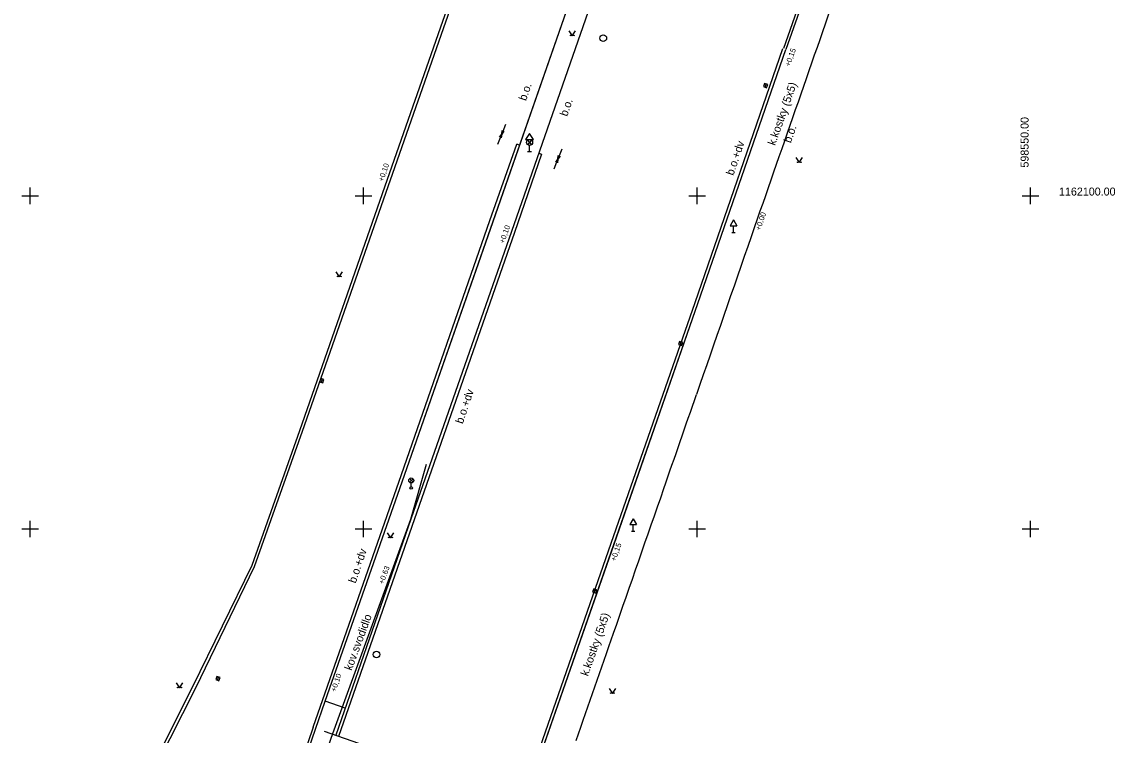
# Model space of a CAD drawing. Extents: x -599151 to -598424, y -1163476 to -1161924.
# Drawn here: x -598625.6 to -598543.7, y -1162140.5 to -1162086.9 of the extents above; entities that cross this region are included whole.
import ezdxf

# ---------------------------------------------------------------- set-up
doc = ezdxf.new("R2010")
doc.units = 0
for name, color, linetype in [('Vrstva 14', 7, 'Continuous'), ('Vrstva 19', 7, 'Continuous'), ('Vrstva 21', 7, 'Continuous'), ('Vrstva 25', 7, 'Continuous'), ('Vrstva 29', 7, 'Continuous'), ('Vrstva 44', 7, 'Continuous'), ('Vrstva 49', 7, 'Continuous'), ('Vrstva 50', 7, 'Continuous'), ('Vrstva 52', 7, 'Continuous'), ('Vrstva 62', 7, 'Continuous'), ('Vrstva 63', 7, 'Continuous'), ('Vrstva 7', 7, 'Continuous')]:
    doc.layers.add(name, color=color, linetype=linetype)

msp = doc.modelspace()

# ---------------------------------------------------------------- linework, layer by layer
at = {"layer": 'Vrstva 14'}
for points in [[(-598584.609, -1162087.607), (-598584.359, -1162087.982), (-598584.109, -1162087.607)], [(-598567.583, -1162097.133), (-598567.333, -1162097.508), (-598567.083, -1162097.133)], [(-598602.072, -1162105.692), (-598601.822, -1162106.067), (-598601.572, -1162105.692)], [(-598598.233, -1162125.28), (-598597.983, -1162125.655), (-598597.733, -1162125.28)], [(-598614.054, -1162136.539), (-598613.804, -1162136.914), (-598613.554, -1162136.539)], [(-598581.6, -1162136.964), (-598581.35, -1162137.339), (-598581.1, -1162136.964)]]:
    msp.add_lwpolyline(points, dxfattribs=at)
for centre in [(-598584.484, -1162087.957), (-598584.234, -1162087.957), (-598567.458, -1162097.483), (-598567.208, -1162097.483), (-598601.947, -1162106.042), (-598601.697, -1162106.042), (-598598.108, -1162125.63), (-598597.858, -1162125.63), (-598613.929, -1162136.889), (-598613.679, -1162136.889), (-598581.475, -1162137.314), (-598581.225, -1162137.314)]:
    msp.add_circle(centre, 0.025, dxfattribs=at)
at = {"layer": 'Vrstva 19'}
for p, q in [((-598572.26, -1162101.807), (-598572.51, -1162102.24)), ((-598572.26, -1162101.807), (-598572.01, -1162102.24)), ((-598572.51, -1162102.24), (-598572.01, -1162102.24)), ((-598572.385, -1162102.74), (-598572.135, -1162102.74)), ((-598572.26, -1162102.74), (-598572.26, -1162102.24)), ((-598579.8, -1162124.238), (-598580.05, -1162124.671)), ((-598580.05, -1162124.671), (-598579.55, -1162124.671)), ((-598579.8, -1162124.238), (-598579.55, -1162124.671)), ((-598579.8, -1162125.171), (-598579.8, -1162124.671)), ((-598579.925, -1162125.171), (-598579.675, -1162125.171))]:
    msp.add_line(p, q, dxfattribs=at)
at = {"layer": 'Vrstva 21'}
msp.add_lwpolyline([(-598609.96, -1162161.79), (-598608.61, -1162158.34), (-598602.3, -1162140.35), (-598596.47, -1162124.26), (-598595.28, -1162120.14)], dxfattribs=at)
at = {"layer": 'Vrstva 25'}
for p, q in [((-598569.903, -1162091.848), (-598569.817, -1162091.612)), ((-598576.273, -1162111.198), (-598576.187, -1162110.962)), ((-598603.099, -1162113.752), (-598603.181, -1162113.988)), ((-598582.713, -1162129.768), (-598582.627, -1162129.532)), ((-598610.963, -1162136.348), (-598610.877, -1162136.112))]:
    msp.add_line(p, q, dxfattribs=at)
for points in [[(-598569.785, -1162091.89), (-598569.7, -1162091.655), (-598569.935, -1162091.57), (-598570.02, -1162091.805)], [(-598576.155, -1162111.24), (-598576.07, -1162111.005), (-598576.305, -1162110.92), (-598576.39, -1162111.155)], [(-598603.216, -1162113.711), (-598603.299, -1162113.946), (-598603.064, -1162114.029), (-598602.981, -1162113.794)], [(-598582.595, -1162129.81), (-598582.51, -1162129.575), (-598582.745, -1162129.49), (-598582.83, -1162129.725)], [(-598610.845, -1162136.39), (-598610.76, -1162136.155), (-598610.995, -1162136.07), (-598611.08, -1162136.305)]]:
    msp.add_lwpolyline(points, close=True, dxfattribs=at)
for centre in [(-598582.03, -1162088.17), (-598599.03, -1162134.42)]:
    msp.add_circle(centre, 0.25, dxfattribs=at)
at = {"layer": 'Vrstva 29'}
for p, q in [((-598596.562, -1162121.489), (-598596.298, -1162121.225)), ((-598596.294, -1162121.488), (-598596.558, -1162121.223)), ((-598596.43, -1162121.82), (-598596.43, -1162121.545))]:
    msp.add_line(p, q, dxfattribs=at)
for centre, radius in [((-598596.43, -1162121.357), 0.188), ((-598596.43, -1162121.92), 0.1)]:
    msp.add_circle(centre, radius, dxfattribs=at)
at = {"layer": 'Vrstva 44'}
for p, q in [((-598587.41, -1162095.82), (-598587.71, -1162096.164)), ((-598587.71, -1162095.82), (-598587.41, -1162096.164)), ((-598587.56, -1162096.67), (-598587.56, -1162096.22)), ((-598587.71, -1162096.67), (-598587.41, -1162096.67)), ((-598602.961, -1162140.169), (-598585.207, -1162146.35))]:
    msp.add_line(p, q, dxfattribs=at)
msp.add_lwpolyline([(-598587.86, -1162095.764), (-598587.26, -1162095.764), (-598587.56, -1162095.314), (-598587.86, -1162095.764)], dxfattribs=at)
msp.add_circle((-598587.56, -1162095.992), 0.228, dxfattribs=at)
at = {"layer": 'Vrstva 49'}
for p, q in [((-598589.364, -1162094.638), (-598589.65, -1162095.376)), ((-598589.364, -1162094.638), (-598589.65, -1162095.376)), ((-598589.936, -1162096.115), (-598589.65, -1162095.376)), ((-598589.936, -1162096.115), (-598589.65, -1162095.376)), ((-598589.814, -1162095.601), (-598589.65, -1162095.376)), ((-598589.814, -1162095.601), (-598589.65, -1162095.376)), ((-598589.65, -1162095.376), (-598589.679, -1162095.654)), ((-598589.65, -1162095.376), (-598589.679, -1162095.654)), ((-598589.65, -1162095.376), (-598589.622, -1162095.098)), ((-598589.65, -1162095.376), (-598589.622, -1162095.098)), ((-598589.486, -1162095.15), (-598589.65, -1162095.376)), ((-598589.486, -1162095.15), (-598589.65, -1162095.376)), ((-598585.146, -1162096.504), (-598585.431, -1162097.243)), ((-598585.146, -1162096.504), (-598585.431, -1162097.243)), ((-598585.431, -1162097.243), (-598585.403, -1162096.964)), ((-598585.431, -1162097.243), (-598585.403, -1162096.964)), ((-598585.268, -1162097.017), (-598585.431, -1162097.243)), ((-598585.268, -1162097.017), (-598585.431, -1162097.243)), ((-598585.716, -1162097.982), (-598585.431, -1162097.243)), ((-598585.716, -1162097.982), (-598585.431, -1162097.243)), ((-598585.596, -1162097.468), (-598585.431, -1162097.243)), ((-598585.596, -1162097.468), (-598585.431, -1162097.243)), ((-598585.431, -1162097.243), (-598585.46, -1162097.522)), ((-598585.431, -1162097.243), (-598585.46, -1162097.522))]:
    msp.add_line(p, q, dxfattribs=at)
at = {"layer": 'Vrstva 62'}
for p, q in [((-598625, -1162100.625), (-598625, -1162099.375)), ((-598600, -1162100.625), (-598600, -1162099.375)), ((-598575, -1162100.625), (-598575, -1162099.375)), ((-598550, -1162100.625), (-598550, -1162099.375)), ((-598625.625, -1162100), (-598624.375, -1162100)), ((-598600.625, -1162100), (-598599.375, -1162100)), ((-598575.625, -1162100), (-598574.375, -1162100)), ((-598550.625, -1162100), (-598549.375, -1162100)), ((-598625.625, -1162125), (-598624.375, -1162125)), ((-598625, -1162125.625), (-598625, -1162124.375)), ((-598600.625, -1162125), (-598599.375, -1162125)), ((-598600, -1162125.625), (-598600, -1162124.375)), ((-598575.625, -1162125), (-598574.375, -1162125)), ((-598575, -1162125.625), (-598575, -1162124.375)), ((-598550.625, -1162125), (-598549.375, -1162125)), ((-598550, -1162125.625), (-598550, -1162124.375))]:
    msp.add_line(p, q, dxfattribs=at)
at = {"layer": 'Vrstva 63'}
for points in [[(-598559.58, -1162063.97), (-598561.45, -1162069.5), (-598566.35, -1162083.35), (-598568.34, -1162089.02)], [(-598619.53, -1162150.2), (-598612.81, -1162136.81), (-598608.35, -1162127.72), (-598604.78, -1162117.61), (-598598.22, -1162098.74), (-598591.99, -1162080.94)], [(-598616.67, -1162177.49), (-598604.34, -1162142.13), (-598602.88, -1162137.92), (-598596.94, -1162120.97), (-598583.85, -1162083.4)], [(-598582.42, -1162083.99), (-598588.91, -1162102.67), (-598596.47, -1162124.26), (-598602.09, -1162140.47)], [(-598601.26, -1162183.73), (-598587.93, -1162145.4), (-598574.93, -1162108.09), (-598568.34, -1162089.02)]]:
    msp.add_lwpolyline(points, dxfattribs=at)
at = {"layer": 'Vrstva 7'}
for points in [[(-598548.319, -1162031.383), (-598550.669, -1162038.044), (-598552.049, -1162042.014), (-598552.959, -1162044.584), (-598555.259, -1162051.174), (-598558.601, -1162060.571), (-598558.661, -1162060.801), (-598559.098, -1162062.033), (-598559.769, -1162063.904), (-598561.639, -1162069.435), (-598566.539, -1162083.284), (-598568.529, -1162088.954)], [(-598548.13, -1162031.45), (-598550.48, -1162038.11), (-598551.86, -1162042.08), (-598552.77, -1162044.65), (-598555.07, -1162051.24), (-598558.41, -1162060.63), (-598558.47, -1162060.86), (-598558.91, -1162062.1), (-598559.58, -1162063.97), (-598561.45, -1162069.5), (-598566.35, -1162083.35), (-598568.34, -1162089.02)], [(-598608.35, -1162127.72), (-598604.78, -1162117.61), (-598598.22, -1162098.74), (-598591.99, -1162080.94)], [(-598608.17, -1162127.808), (-598604.58, -1162117.67), (-598597.99, -1162098.8), (-598591.77, -1162081)], [(-598602.88, -1162137.92), (-598596.94, -1162120.97), (-598590.3, -1162101.93), (-598583.85, -1162083.4)], [(-598582.42, -1162083.99), (-598588.91, -1162102.67), (-598596.47, -1162124.26), (-598602.09, -1162140.47)], [(-598601.445, -1162183.654), (-598594.65, -1162164.05), (-598588.14, -1162145.33), (-598581.43, -1162126.06), (-598575.13, -1162108.01), (-598568.57, -1162088.94)], [(-598601.26, -1162183.73), (-598594.44, -1162164.13), (-598587.93, -1162145.4), (-598581.22, -1162126.15), (-598574.93, -1162108.09), (-598568.34, -1162089.02)], [(-598603.78, -1162139.88), (-598597.16, -1162120.9), (-598590.55, -1162101.85), (-598588.52, -1162096.11)], [(-598588.301, -1162096.186), (-598588.52, -1162096.11)], [(-598586.874, -1162096.809), (-598586.67, -1162096.88), (-598588.68, -1162102.76), (-598601.88, -1162140.559)], [(-598619.53, -1162150.2), (-598612.81, -1162136.81), (-598608.35, -1162127.72)], [(-598619.351, -1162150.29), (-598612.58, -1162136.91), (-598608.17, -1162127.808)], [(-598604.34, -1162142.13), (-598602.88, -1162137.92)], [(-598601.392, -1162138.456), (-598602.88, -1162137.92)]]:
    msp.add_lwpolyline(points, dxfattribs=at)
for centre, radius, start, end in [((1482166.042, -1885789.617), 2202995.377, 160.821652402, 160.822168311), ((-576016.551, -1169920.374), 23870.714, 160.8838047, 160.9138586), ((-598425.121, -1162153.619), 154.338, 160.82217, 160.88288), ((-606656.733, -1159318.559), 8551.798, 340.8637528, 340.9138614), ((-624670.429, -1153067.95), 27619.135, 340.8398417, 340.8636701), ((-612939.478, -1157143.951), 15200.238, 340.8077361, 340.839826), ((-566759.33, -1173270.455), 33733.643, 160.7339722, 160.8015194)]:
    msp.add_arc(centre, radius, start, end, dxfattribs=at)

# ---------------------------------------------------------------- texts
at = {"layer": 'Vrstva 49'}
for s, height, rotation, p in [('b.o.', 0.6, 70.8078, (-598587.825, -1162092.914)), ('k.kostky (5x5)', 0.6, 70.64007, (-598569.152, -1162096.264)), ('b.o.', 0.6, 70.8078, (-598584.742, -1162094.085)), ('b.o.', 0.6, 70.82195, (-598567.969, -1162096.077)), ('b.o.+dv', 0.6, 71.46297, (-598572.276, -1162098.517)), ('b.o.+dv', 0.6, 71.46297, (-598592.57, -1162117.149)), ('b.o.+dv', 0.6, 71.46297, (-598600.596, -1162129.115)), ('kov.svodidlo', 0.59995, 69.79513, (-598600.898, -1162135.664)), ('k.kostky (5x5)', 0.6, 70.64007, (-598583.184, -1162136.08))]:
    msp.add_text(s, height=height, rotation=rotation, dxfattribs=at).set_placement(p)
at = {"layer": 'Vrstva 50'}
for s, rotation, p in [('+0,15', 70.44636, (-598568.043, -1162090.324)), ('+0,10', 70.8078, (-598598.537, -1162098.96)), ('+0,00', 70.97832, (-598570.267, -1162102.631)), ('+0,10', 70.8078, (-598589.462, -1162103.603)), ('+0,15', 70.44636, (-598581.119, -1162127.452)), ('+0.63', 69.97634, (-598598.515, -1162129.172)), ('+0,10', 70.8078, (-598602.104, -1162137.255))]:
    msp.add_text(s, height=0.4, rotation=rotation, dxfattribs=at).set_placement(p)
at = {"layer": 'Vrstva 52'}
msp.add_text('598550.00', height=0.6, rotation=90, dxfattribs=at).set_placement((-598550.142, -1162097.878))
msp.add_text('1162100.00', height=0.6, dxfattribs=at).set_placement((-598547.861, -1162099.98))

doc.saveas('drawing.dxf')
